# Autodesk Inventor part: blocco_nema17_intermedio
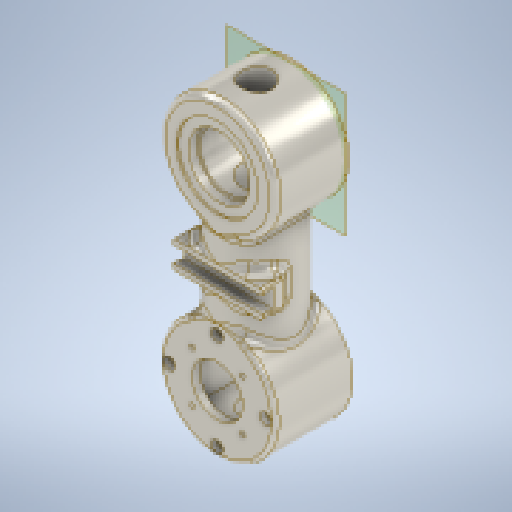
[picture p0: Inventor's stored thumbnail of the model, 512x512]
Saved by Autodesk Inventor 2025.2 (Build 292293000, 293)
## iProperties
Created: 2025-05
Part Number: blocco_nema17_intermedio
Material: Titanio
Document SubType Name: Modeling
Designer: 18907419
Density: 4.51 g/cm^3
Appearance: Titanio
alezza: 50,000 mm
Author: 18907419
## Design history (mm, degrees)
sketch "Schizzo1"
  geometry: C1 r 35 at (0, 0); 1 further point
  constraints: 1 centre point, 1 coincident
  dimensions: "d0" = 70 diameter of C1
extrude "Estrusione1" new body sketch "Schizzo1" stored distance "d1" = 40; taper "d2" = 0 deg
sketch "Schizzo2"
  geometry: L1 (-35, -20)-(35, -20) reference; L2 (35, 20)-(-35, 20) reference; L3 (35, -20)-(35, 20) reference; L4 (-35, -20)-(-35, 20) reference; C1 r 20 at (0, 0); 1 further point
  constraints: 1 centre point, 1 coincident
  dimensions: "d52" = 40 diameter of C1
extrude "Estrusione2" join sketch "Schizzo2" taper "d4" = 0 deg
sketch "Schizzo7"
  geometry: C1 r 8 at (0, 0); 1 further point
  constraints: 1 centre point, 1 coincident
  dimensions: "d19" = 16 diameter of C1
extrude "Estrusione7" cut sketch "Schizzo7" distance "d20" = 95.5; taper "d21" = 0 deg
sketch "Schizzo12"
  geometry: L1 (-17.5, 17.5)-(17.5, 17.5); L2 (17.5, 17.5)-(17.5, -17.5); L3 (17.5, -17.5)-(-17.5, -17.5); L4 (-17.5, -17.5)-(-17.5, 17.5); L5 (-17.5, 17.5)-(17.5, -17.5); L6 (17.5, 17.5)-(-17.5, -17.5); 1 further point
  constraints: 12 end point, 2 midpoint, 2 parallel, 1 horizontal, 1 perpendicular
  dimensions: "d38" = 35 distance of L2.end L3.end; "d39" = 35 distance of L1.end L2.end
extrude "Estrusione11" cut sketch "Schizzo12" distance "d40" = 60; taper "d41" = 0 deg
mirror "Speculare2"
sketch "Schizzo13"
  geometry: C1 r 16 at (0, 0); 1 further point
  constraints: 1 centre point
  dimensions: "d42" = 32 diameter of C1
extrude "Estrusione12" cut sketch "Schizzo13" extent not by distance; stored distance "d43" = 32; taper "d44" = 0 deg
mirror "Speculare3"
sketch "Schizzo18"
  geometry: L1 (-17.5, -17.5)-(-17.5, 17.5) reference; L2 (-17.5, 17.5)-(17.5, 17.5) reference; L3 (17.5, 17.5)-(17.5, -17.5) reference; L4 (17.5, -17.5)-(-17.5, -17.5) reference; C1 r 13 at (0, 0); C2 r 1.23 at (13.1, 13.1) reference; C3 r 1.23 at (13.1, -12.9) reference; C4 r 1.23 at (-12.9, -12.9) reference; C5 r 1.23 at (-12.9, 13.1) reference; 3 further points
  constraints: 1 centre point, 1 coincident, 1 vertical alignment
  dimensions: "d63" = 26 diameter of C1
  node "Linea chiusa proiettata5"
  node "Riferimento1"
  node "Riferimento2"
  node "Riferimento3"
  node "Riferimento4"
node "Piano di lavoro2"
extrude "Estrusione16" join sketch "Schizzo18" stored distance "d64" = 3; taper "d65" = 0 deg
sketch "Schizzo19"
  geometry: C1 r 1.7 at (0, 25) reference; 1 further point
hole "Foro3" sketch "Schizzo19" at (0, 25) diameter "d66" = 3.4; stored, may be unused: countersink angle "d70" = 90 deg, drill point angle "d72" = 118 deg; dims "d67" = 6, "d68" = 6.3, "d69" = 3.4, "d71" = 8
sketch "Schizzo20"
  geometry: C1 r 1.7 at (0, 25) reference; 2 further points
  constraints: 1 coincident
hole "Foro4" sketch "Schizzo20" at (0, 25) diameter "d76" = 3.4; stored, may be unused: countersink angle "d80" = 90 deg, drill point angle "d82" = 118 deg; dims "d77" = 6, "d78" = 6, "d79" = 3, "d81" = 8
pattern_circular "Serie circolare2" dims "d84" = 360 deg
fillet "Raccordo2" dims "d88" = 3
fillet "Raccordo3" dims "d89" = 5
fillet "Raccordo4" dims "d90" = 2
fillet "Raccordo5" dims "d91" = 2
node "Piano di lavoro3"
sketch "Schizzo23"
  geometry: L1 (0, 0)-(0, 100); L2 (20, 31.225)-(20, 68.775) reference; L3 (-23, 57)-(23, 57); L4 (23, 57)-(23, 43); L5 (23, 43)-(-23, 43); L6 (-23, 43)-(-23, 57); L7 (-23, 57)-(23, 43); L8 (23, 57)-(-23, 43); C1 r 10.7 at (0, 0) reference; C2 r 16 at (0, 100) reference; 2 further points
  constraints: 14 end point, 3 midpoint, 2 parallel, 1 coincident, 1 horizontal, 1 perpendicular, 1 vertical
  dimensions: "d104" = 46 distance of L4.end L5.end; "d105" = 14 distance of L3.end L4.end
extrude "Estrusione19" join sketch "Schizzo23" distance "d99" = 7; taper "d101" = 0 deg; dims "d100" = 6, "d102" = 0
fillet "Raccordo6" dims "d106" = 5
fillet "Raccordo7" dims "d107" = 5
sketch "Schizzo24"
  geometry: L1 (-10.38, 0)-(-10.38, 14) reference; L2 (-10.38, 0)-(0, 0) reference; L3 (0, 14)-(0, 0) reference; L4 (-10.38, 14)-(0, 14) reference; L5 (0, 7)-(-10.38, 7); L6 (0, 11)-(-6, 12.058); L7 (-6, 12.058)-(-6, 7); L8 (0, 3)-(-6, 1.942); L9 (-6, 1.942)-(-6, 7); L10 (0, 14)-(0, 0) reference; 3 further points
  constraints: 10 end point, 3 midpoint, 2 point on line, 2 symmetric about line, 1 perpendicular
  dimensions: "d108" = 6 distance between parallel lines of L7 L3; "d109" = 80 deg angle of L7 L6; "d113" = 4 distance of point (0, 7) L6.start
extrude "Estrusione20" cut sketch "Schizzo24" extent not by distance; stored distance "d110" = 0; taper "d111" = 0 deg
node "Piano di lavoro4"
sketch "Schizzo25"
  geometry: C1 r 14.5 at (0, 0); C2 r 16 at (0, 0) reference; 1 further point
  constraints: 1 centre point
  dimensions: "d115" = 29 diameter of C1
extrude "Estrusione21" join sketch "Schizzo25" distance "d116" = 30; taper "d117" = 0 deg
sketch "Schizzo26"
  geometry: C1 r 21 at (0, 0); 1 further point
  constraints: 1 centre point
  dimensions: "d118" = 42 diameter of C1
extrude "Estrusione22" cut sketch "Schizzo26" distance "d119" = 1; taper "d120" = 0 deg
fillet "Raccordo9" dims "d121" = 1
fillet "Raccordo10" dims "d122" = 5
sketch "Schizzo27"
  geometry: C1 r 8 at (17.5, 20) reference; C2 r 8 at (17.5, 20); C3 r 10 at (17.5, 20); 1 further point
  constraints: 2 centre point, 2 coincident, 1 concentric
  dimensions: "d127" = 20 diameter of C3
extrude "Estrusione23" cut sketch "Schizzo27" extent not by distance; stored distance "d123" = 0; taper "d124" = 0 deg
node "Solido1"
node "Linea chiusa proiettata1"
node "Riferimento5"
node "Riferimento7"
node "Linea chiusa proiettata7"
other parameters: "d92" = 13, "d114" = -4.5
